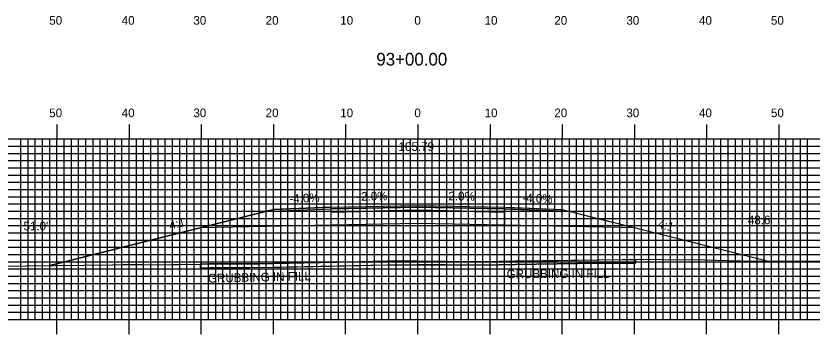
# Model space of a CAD drawing. Extents: x 1764939 to 1765282, y 442591 to 442811.
# Drawn here: x 1765049.2 to 1765159.5, y 442691.7 to 442735.7 of the extents above; entities that cross this region are included whole.
import ezdxf

# ---------------------------------------------------------------- set-up
doc = ezdxf.new("R2010")
doc.units = 0
for name, color, linetype in [('ANNOTATION', 7, 'Continuous'), ('D_Roadway_Centerline', 7, 'Continuous'), ('D_Roadway_Centerline_Text', 7, 'Continuous'), ('D_Roadway_Edge_Shoulder', 7, 'Continuous'), ('D_Roadway_Edge_TW', 7, 'Continuous'), ('D_Roadway_Pavement', 7, 'Continuous'), ('D_Roadway_SlopeLines', 7, 'Continuous'), ('D_Roadway_SubGrade', 7, 'Continuous'), ('D_Text_Standard', 7, 'Continuous'), ('GRUBBING IN FILL', 7, 'Continuous'), ('H_V ANNOTATION', 7, 'Continuous'), ('MAJOR', 7, 'Continuous'), ('MINOR', 7, 'Continuous'), ('S_Roadway_Centerline', 7, 'Continuous')]:
    doc.layers.add(name, color=color, linetype=linetype)

msp = doc.modelspace()

# ---------------------------------------------------------------- linework, layer by layer
at = {"layer": 'D_Roadway_Centerline'}
msp.add_lwpolyline([(1765053.88, 442701.15), (1765072.86, 442705.9), (1765074.68, 442706.35), (1765084.86, 442708.9), (1765086.04, 442708.94), (1765092.85, 442709.22), (1765092.86, 442709.22), (1765092.86, 442709.22), (1765104.86, 442709.46), (1765104.86, 442709.46), (1765116.86, 442709.22), (1765118.21, 442709.16), (1765124.86, 442708.9), (1765129.41, 442707.76), (1765135.03, 442706.35), (1765147.89, 442703.14), (1765153.43, 442701.75)], dxfattribs=at)
at = {"layer": 'D_Roadway_Edge_Shoulder'}
for points in [[(1765092.86, 442709.22), (1765084.86, 442708.9), (1765084.86, 442708.65), (1765092.86, 442708.97)], [(1765116.86, 442709.22), (1765124.86, 442708.9), (1765124.86, 442708.65), (1765116.86, 442708.97)]]:
    msp.add_lwpolyline(points, close=True, dxfattribs=at)
at = {"layer": 'D_Roadway_Edge_TW'}
msp.add_lwpolyline([(1765092.86, 442708.97), (1765092.86, 442709.22), (1765104.86, 442709.46), (1765116.86, 442709.22), (1765116.86, 442708.97), (1765104.86, 442709.21)], close=True, dxfattribs=at)
at = {"layer": 'D_Roadway_Pavement'}
msp.add_lwpolyline([(1765092.86, 442708.55), (1765092.86, 442708.97), (1765104.86, 442709.21), (1765116.86, 442708.97), (1765116.86, 442708.55), (1765104.86, 442708.79)], close=True, dxfattribs=at)
at = {"layer": 'D_Roadway_SlopeLines'}
for points in [[(1765084.86, 442708.9), (1765074.68, 442706.35), (1765072.86, 442705.9), (1765053.88, 442701.15)], [(1765124.86, 442708.9), (1765135.03, 442706.35), (1765153.43, 442701.75)]]:
    msp.add_lwpolyline(points, dxfattribs=at)
at = {"layer": 'D_Roadway_SubGrade'}
for points in [[(1765092.86, 442706.72), (1765074.68, 442706.35), (1765084.86, 442708.9), (1765084.86, 442708.65), (1765092.86, 442708.97), (1765104.86, 442709.21), (1765116.86, 442708.97), (1765124.86, 442708.65), (1765124.86, 442708.9), (1765135.03, 442706.35), (1765116.86, 442706.72), (1765104.86, 442706.96)], [(1765092.86, 442706.72), (1765092.86, 442708.55), (1765104.86, 442708.79), (1765116.86, 442708.55), (1765116.86, 442706.72), (1765104.86, 442706.96)]]:
    msp.add_lwpolyline(points, close=True, dxfattribs=at)
at = {"layer": 'GRUBBING IN FILL'}
for p, q in [((1765074.68, 442701.34), (1765074.68, 442700.84)), ((1765135.03, 442701.99), (1765135.03, 442701.49))]:
    msp.add_line(p, q, dxfattribs=at)
for points in [[(1765074.68, 442700.84), (1765078.13, 442700.89), (1765081.51, 442700.89), (1765085.94, 442700.94), (1765094.85, 442701.12), (1765100.62, 442701.25), (1765103.43, 442701.25), (1765104.86, 442701.24), (1765104.86, 442701.74), (1765100.62, 442701.75), (1765094.84, 442701.62), (1765089.06, 442701.5), (1765082.8, 442701.39), (1765078.12, 442701.39), (1765076.04, 442701.37), (1765074.68, 442701.34)], [(1765074.68, 442700.84), (1765078.13, 442700.89), (1765081.51, 442700.89), (1765085.94, 442700.94), (1765094.85, 442701.12), (1765100.62, 442701.25), (1765103.43, 442701.25), (1765104.86, 442701.24), (1765104.86, 442701.74), (1765100.62, 442701.75), (1765094.84, 442701.62), (1765089.06, 442701.5), (1765082.8, 442701.39), (1765078.12, 442701.39), (1765076.04, 442701.37), (1765074.68, 442701.34)], [(1765104.86, 442701.74), (1765108.66, 442701.73), (1765113.88, 442701.7), (1765116.14, 442701.74), (1765124.17, 442701.86), (1765129.94, 442701.95), (1765135.03, 442701.99), (1765135.03, 442701.49), (1765132.49, 442701.47), (1765129.94, 442701.45), (1765124.18, 442701.36), (1765118.41, 442701.28), (1765113.88, 442701.2), (1765108.66, 442701.23), (1765104.86, 442701.24)], [(1765104.86, 442701.74), (1765108.66, 442701.73), (1765113.88, 442701.7), (1765116.14, 442701.74), (1765124.17, 442701.86), (1765129.94, 442701.95), (1765135.03, 442701.99), (1765135.03, 442701.49), (1765132.49, 442701.47), (1765129.94, 442701.45), (1765124.18, 442701.36), (1765118.41, 442701.28), (1765113.88, 442701.2), (1765108.66, 442701.23), (1765104.86, 442701.24)]]:
    msp.add_lwpolyline(points, close=True, dxfattribs=at)
msp.add_lwpolyline([(1765074.68, 442700.84), (1765075, 442700.84), (1765076.04, 442700.87), (1765080.21, 442700.9), (1765082.8, 442700.89), (1765089.07, 442701), (1765100.62, 442701.25), (1765101.45, 442701.25), (1765103.43, 442701.25), (1765113.88, 442701.2), (1765118.41, 442701.28), (1765129.94, 442701.45), (1765135.03, 442701.49)], dxfattribs=at)
at = {"layer": 'MAJOR'}
for p, q in [((1765054.86, 442720.67), (1765054.86, 442718.67)), ((1765064.86, 442720.67), (1765064.86, 442718.67)), ((1765074.86, 442720.67), (1765074.86, 442718.67)), ((1765084.86, 442720.67), (1765084.86, 442718.67)), ((1765094.86, 442720.67), (1765094.86, 442718.67)), ((1765104.86, 442720.67), (1765104.86, 442718.67)), ((1765114.86, 442720.67), (1765114.86, 442718.67)), ((1765124.86, 442720.67), (1765124.86, 442718.67)), ((1765134.86, 442720.67), (1765134.86, 442718.67)), ((1765144.86, 442720.67), (1765144.86, 442718.67)), ((1765154.86, 442720.67), (1765154.86, 442718.67)), ((1764964.86, 442718.67), (1765244.86, 442718.67)), ((1764964.86, 442718.67), (1765244.86, 442718.67)), ((1765054.86, 442693.67), (1765054.86, 442718.67)), ((1765064.86, 442693.67), (1765064.86, 442718.67)), ((1765074.86, 442693.67), (1765074.86, 442718.67)), ((1765084.86, 442693.67), (1765084.86, 442718.67)), ((1765094.86, 442693.67), (1765094.86, 442718.67)), ((1765104.86, 442693.67), (1765104.86, 442718.67)), ((1765114.86, 442693.67), (1765114.86, 442718.67)), ((1765124.86, 442693.67), (1765124.86, 442718.67)), ((1765134.86, 442693.67), (1765134.86, 442718.67)), ((1765144.86, 442693.67), (1765144.86, 442718.67)), ((1765154.86, 442693.67), (1765154.86, 442718.67)), ((1764964.86, 442713.67), (1765244.86, 442713.67)), ((1764964.86, 442708.67), (1765244.86, 442708.67)), ((1764964.86, 442703.67), (1765244.86, 442703.67)), ((1764964.86, 442698.67), (1765244.86, 442698.67)), ((1764964.86, 442693.67), (1765244.86, 442693.67)), ((1764964.86, 442693.67), (1765244.86, 442693.67)), ((1765054.86, 442691.66), (1765054.86, 442693.67)), ((1765064.86, 442691.66), (1765064.86, 442693.67)), ((1765074.86, 442691.66), (1765074.86, 442693.67)), ((1765084.86, 442691.66), (1765084.86, 442693.67)), ((1765094.86, 442691.66), (1765094.86, 442693.67)), ((1765104.86, 442691.66), (1765104.86, 442693.67)), ((1765114.86, 442691.66), (1765114.86, 442693.67)), ((1765124.86, 442691.66), (1765124.86, 442693.67)), ((1765134.86, 442691.66), (1765134.86, 442693.67)), ((1765144.86, 442691.66), (1765144.86, 442693.67)), ((1765154.86, 442691.66), (1765154.86, 442693.67))]:
    msp.add_line(p, q, dxfattribs=at)
at = {"layer": 'MINOR'}
for p, q in [((1765049.86, 442693.67), (1765049.86, 442718.67)), ((1765050.86, 442693.67), (1765050.86, 442718.67)), ((1765051.86, 442693.67), (1765051.86, 442718.67)), ((1765052.86, 442693.67), (1765052.86, 442718.67)), ((1765053.86, 442693.67), (1765053.86, 442718.67)), ((1765055.86, 442693.67), (1765055.86, 442718.67)), ((1765056.86, 442693.67), (1765056.86, 442718.67)), ((1765057.86, 442693.67), (1765057.86, 442718.67)), ((1765058.86, 442693.67), (1765058.86, 442718.67)), ((1765059.86, 442693.67), (1765059.86, 442718.67)), ((1765060.86, 442693.67), (1765060.86, 442718.67)), ((1765061.86, 442693.67), (1765061.86, 442718.67)), ((1765062.86, 442693.67), (1765062.86, 442718.67)), ((1765063.86, 442693.67), (1765063.86, 442718.67)), ((1765065.86, 442693.67), (1765065.86, 442718.67)), ((1765066.86, 442693.67), (1765066.86, 442718.67)), ((1765067.86, 442693.67), (1765067.86, 442718.67)), ((1765068.86, 442693.67), (1765068.86, 442718.67)), ((1765069.86, 442693.67), (1765069.86, 442718.67)), ((1765070.86, 442693.67), (1765070.86, 442718.67)), ((1765071.86, 442693.67), (1765071.86, 442718.67)), ((1765072.86, 442693.67), (1765072.86, 442718.67)), ((1765073.86, 442693.67), (1765073.86, 442718.67)), ((1765075.86, 442693.67), (1765075.86, 442718.67)), ((1765076.86, 442693.67), (1765076.86, 442718.67)), ((1765077.86, 442693.67), (1765077.86, 442718.67)), ((1765078.86, 442693.67), (1765078.86, 442718.67)), ((1765079.86, 442693.67), (1765079.86, 442718.67)), ((1765080.86, 442693.67), (1765080.86, 442718.67)), ((1765081.86, 442693.67), (1765081.86, 442718.67)), ((1765082.86, 442693.67), (1765082.86, 442718.67)), ((1765083.86, 442693.67), (1765083.86, 442718.67)), ((1765085.86, 442693.67), (1765085.86, 442718.67)), ((1765086.86, 442693.67), (1765086.86, 442718.67)), ((1765087.86, 442693.67), (1765087.86, 442718.67)), ((1765088.86, 442693.67), (1765088.86, 442718.67)), ((1765089.86, 442693.67), (1765089.86, 442718.67)), ((1765090.86, 442693.67), (1765090.86, 442718.67)), ((1765091.86, 442693.67), (1765091.86, 442718.67)), ((1765092.86, 442693.67), (1765092.86, 442718.67)), ((1765093.86, 442693.67), (1765093.86, 442718.67)), ((1765095.86, 442693.67), (1765095.86, 442718.67)), ((1765096.86, 442693.67), (1765096.86, 442718.67)), ((1765097.86, 442693.67), (1765097.86, 442718.67)), ((1765098.86, 442693.67), (1765098.86, 442718.67)), ((1765099.86, 442693.67), (1765099.86, 442718.67)), ((1765100.86, 442693.67), (1765100.86, 442718.67)), ((1765101.86, 442693.67), (1765101.86, 442718.67)), ((1765102.86, 442693.67), (1765102.86, 442718.67)), ((1765103.86, 442693.67), (1765103.86, 442718.67)), ((1765105.86, 442693.67), (1765105.86, 442718.67)), ((1765106.86, 442693.67), (1765106.86, 442718.67)), ((1765107.86, 442693.67), (1765107.86, 442718.67)), ((1765108.86, 442693.67), (1765108.86, 442718.67)), ((1765109.86, 442693.67), (1765109.86, 442718.67)), ((1765110.86, 442693.67), (1765110.86, 442718.67)), ((1765111.86, 442693.67), (1765111.86, 442718.67)), ((1765112.86, 442693.67), (1765112.86, 442718.67)), ((1765113.86, 442693.67), (1765113.86, 442718.67)), ((1765115.86, 442693.67), (1765115.86, 442718.67)), ((1765116.86, 442693.67), (1765116.86, 442718.67)), ((1765117.86, 442693.67), (1765117.86, 442718.67)), ((1765118.86, 442693.67), (1765118.86, 442718.67)), ((1765119.86, 442693.67), (1765119.86, 442718.67)), ((1765120.86, 442693.67), (1765120.86, 442718.67)), ((1765121.86, 442693.67), (1765121.86, 442718.67)), ((1765122.86, 442693.67), (1765122.86, 442718.67)), ((1765123.86, 442693.67), (1765123.86, 442718.67)), ((1765125.86, 442693.67), (1765125.86, 442718.67)), ((1765126.86, 442693.67), (1765126.86, 442718.67)), ((1765127.86, 442693.67), (1765127.86, 442718.67)), ((1765128.86, 442693.67), (1765128.86, 442718.67)), ((1765129.86, 442693.67), (1765129.86, 442718.67)), ((1765130.86, 442693.67), (1765130.86, 442718.67)), ((1765131.86, 442693.67), (1765131.86, 442718.67)), ((1765132.86, 442693.67), (1765132.86, 442718.67)), ((1765133.86, 442693.67), (1765133.86, 442718.67)), ((1765135.86, 442693.67), (1765135.86, 442718.67)), ((1765136.86, 442693.67), (1765136.86, 442718.67)), ((1765137.86, 442693.67), (1765137.86, 442718.67)), ((1765138.86, 442693.67), (1765138.86, 442718.67)), ((1765139.86, 442693.67), (1765139.86, 442718.67)), ((1765140.86, 442693.67), (1765140.86, 442718.67)), ((1765141.86, 442693.67), (1765141.86, 442718.67)), ((1765142.86, 442693.67), (1765142.86, 442718.67)), ((1765143.86, 442693.67), (1765143.86, 442718.67)), ((1765145.86, 442693.67), (1765145.86, 442718.67)), ((1765146.86, 442693.67), (1765146.86, 442718.67)), ((1765147.86, 442693.67), (1765147.86, 442718.67)), ((1765148.86, 442693.67), (1765148.86, 442718.67)), ((1765149.86, 442693.67), (1765149.86, 442718.67)), ((1765150.86, 442693.67), (1765150.86, 442718.67)), ((1765151.86, 442693.67), (1765151.86, 442718.67)), ((1765152.86, 442693.67), (1765152.86, 442718.67)), ((1765153.86, 442693.67), (1765153.86, 442718.67)), ((1765155.86, 442693.67), (1765155.86, 442718.67)), ((1765156.86, 442693.67), (1765156.86, 442718.67)), ((1765157.86, 442693.67), (1765157.86, 442718.67)), ((1765158.86, 442693.67), (1765158.86, 442718.67)), ((1764964.86, 442717.67), (1765244.86, 442717.67)), ((1764964.86, 442716.67), (1765244.86, 442716.67)), ((1764964.86, 442715.67), (1765244.86, 442715.67)), ((1764964.86, 442714.67), (1765244.86, 442714.67)), ((1764964.86, 442712.67), (1765244.86, 442712.67)), ((1764964.86, 442711.67), (1765244.86, 442711.67)), ((1764964.86, 442710.67), (1765244.86, 442710.67)), ((1764964.86, 442709.67), (1765244.86, 442709.67)), ((1764964.86, 442707.67), (1765244.86, 442707.67)), ((1764964.86, 442706.67), (1765244.86, 442706.67)), ((1764964.86, 442705.67), (1765244.86, 442705.67)), ((1764964.86, 442704.67), (1765244.86, 442704.67)), ((1764964.86, 442702.67), (1765244.86, 442702.67)), ((1764964.86, 442701.67), (1765244.86, 442701.67)), ((1764964.86, 442700.67), (1765244.86, 442700.67)), ((1764964.86, 442699.67), (1765244.86, 442699.67)), ((1764964.86, 442697.67), (1765244.86, 442697.67)), ((1764964.86, 442696.67), (1765244.86, 442696.67)), ((1764964.86, 442695.67), (1765244.86, 442695.67)), ((1764964.86, 442694.67), (1765244.86, 442694.67))]:
    msp.add_line(p, q, dxfattribs=at)
at = {"layer": 'S_Roadway_Centerline'}
msp.add_lwpolyline([(1765046.64, 442701.06), (1765062.57, 442701.25), (1765064.05, 442701.28), (1765064.31, 442701.28), (1765066.62, 442701.27), (1765067.76, 442701.26), (1765070.74, 442701.27), (1765071.91, 442701.28), (1765074.99, 442701.34), (1765076.04, 442701.37), (1765080.21, 442701.4), (1765082.8, 442701.39), (1765089.06, 442701.5), (1765100.62, 442701.75), (1765101.45, 442701.75), (1765103.43, 442701.75), (1765113.88, 442701.7), (1765118.4, 442701.78), (1765129.94, 442701.95), (1765136.51, 442702.01), (1765138.96, 442701.99), (1765144.62, 442701.91), (1765151.3, 442701.73), (1765154.28, 442701.76), (1765164, 442701.76)], dxfattribs=at)

# ---------------------------------------------------------------- texts
at = {"layer": 'ANNOTATION'}
for s, rotation, p in [('-4.0%', 2.2906, (1765087.08, 442709.79)), ('-2.0%', 1.1458, (1765096.47, 442710.09)), ('-2.0%', 358.8542, (1765108.55, 442710.18)), ('-4.0%', 357.7095, (1765119.32, 442709.92)), ('4:1', 14.0363, (1765070.56, 442706.09)), ('4:1', 345.9634, (1765138.01, 442706.38))]:
    msp.add_text(s, height=1.2, rotation=rotation, dxfattribs=at).set_placement(p)
at = {"layer": 'D_Roadway_Centerline'}
for s, p in [('C', (1765104.85, 442709.46)), ('L', (1765104.86, 442709.45))]:
    msp.add_text(s, height=0.0146, dxfattribs=at).set_placement(p)
at = {"layer": 'D_Roadway_Centerline_Text'}
msp.add_text('105.79', height=1.2, dxfattribs=at).set_placement((1765102.19, 442717.01))
at = {"layer": 'D_Text_Standard'}
for s, p in [("48.6'", (1765150.59, 442706.85)), ("51.0'", (1765050.22, 442706.01))]:
    msp.add_text(s, height=1.2, dxfattribs=at).set_placement(p)
at = {"layer": 'GRUBBING IN FILL'}
for rotation, p in [(1.2837, (1765075.79, 442698.78)), (0.2535, (1765117.17, 442699.38))]:
    msp.add_text('GRUBBING IN FILL', height=1.2, rotation=rotation, dxfattribs=at).set_placement(p)
at = {"layer": 'H_V ANNOTATION'}
for s, height, p in [('50', 1.2, (1765053.79, 442734.47)), ('40', 1.2, (1765063.83, 442734.47)), ('30', 1.2, (1765073.76, 442734.47)), ('20', 1.2, (1765083.77, 442734.47)), ('10', 1.2, (1765094.11, 442734.47)), ('0', 1.2, (1765104.38, 442734.47)), ('10', 1.2, (1765114.11, 442734.47)), ('20', 1.2, (1765123.77, 442734.47)), ('30', 1.2, (1765133.76, 442734.47)), ('40', 1.2, (1765143.83, 442734.47)), ('50', 1.2, (1765153.79, 442734.47)), ('93+00.00', 1.75, (1765099.11, 442728.82)), ('50', 1.2, (1765053.79, 442721.67)), ('40', 1.2, (1765063.83, 442721.67)), ('30', 1.2, (1765073.76, 442721.67)), ('20', 1.2, (1765083.77, 442721.67)), ('10', 1.2, (1765094.11, 442721.67)), ('0', 1.2, (1765104.38, 442721.67)), ('10', 1.2, (1765114.11, 442721.67)), ('20', 1.2, (1765123.77, 442721.67)), ('30', 1.2, (1765133.76, 442721.67)), ('40', 1.2, (1765143.83, 442721.67)), ('50', 1.2, (1765153.79, 442721.67))]:
    msp.add_text(s, height=height, dxfattribs=at).set_placement(p)

doc.saveas('drawing.dxf')
